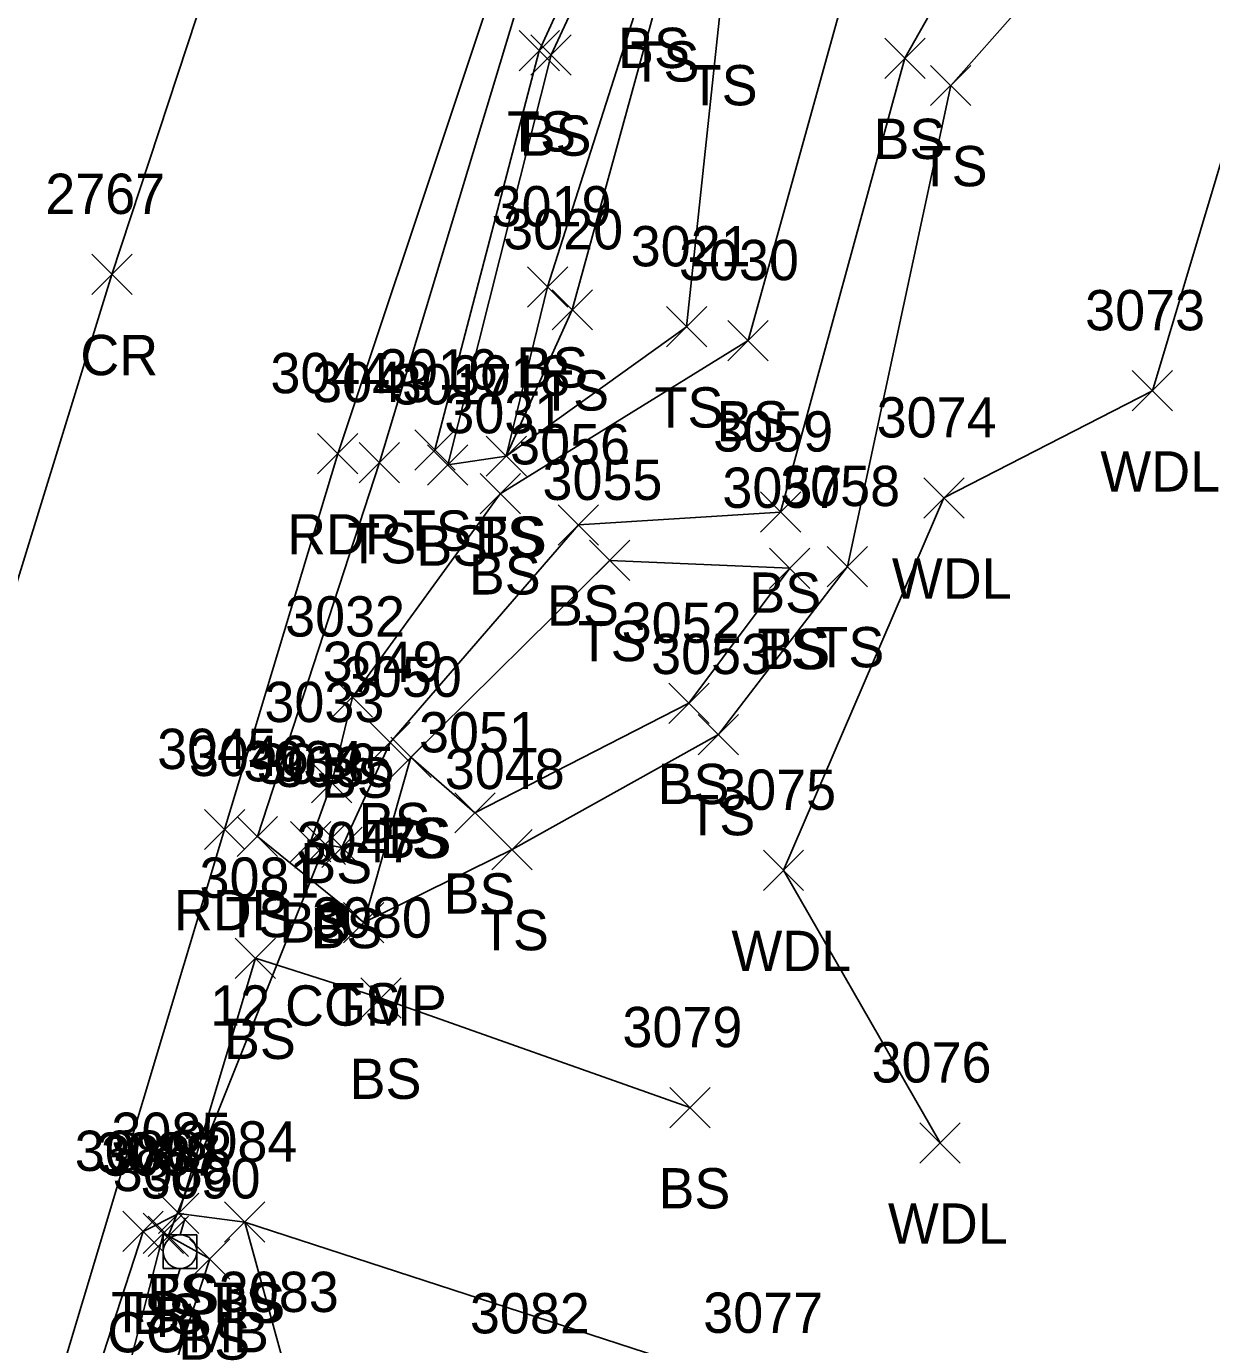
# Model space of a CAD drawing. Extents: x 1678863 to 1683592, y 407783 to 418211.
# Drawn here: x 1680507.9 to 1680566.7, y 415261.2 to 415326.6 of the extents above; entities that cross this region are included whole.
import ezdxf

# ---------------------------------------------------------------- set-up
doc = ezdxf.new("R2010")
doc.units = 0
for name, color, linetype in [('D_A', 7, 'Continuous'), ('D_C', 7, 'Continuous'), ('D_I', 7, 'Continuous'), ('D_TIC', 7, 'Continuous'), ('DCP', 7, 'Continuous'), ('L_A', 7, 'Continuous'), ('L_I', 7, 'Continuous'), ('L_TIC', 7, 'Continuous'), ('LAWA', 7, 'Continuous'), ('LELB', 7, 'Continuous'), ('P_A', 7, 'Continuous'), ('P_I', 7, 'Continuous'), ('P_TIC', 7, 'Continuous'), ('PET', 7, 'Continuous'), ('PRC', 7, 'Continuous'), ('U_A', 7, 'Continuous'), ('U_I', 7, 'Continuous'), ('UP', 7, 'Continuous')]:
    doc.layers.add(name, color=color, linetype=linetype)

msp = doc.modelspace()

# ---------------------------------------------------------------- linework, layer by layer
at = {"layer": 'D_TIC'}
for points in [[(1680521.768, 415285.028), (1680523.768, 415287.028)], [(1680523.768, 415285.028), (1680521.768, 415287.028)], [(1680513.981, 415265.583), (1680515.981, 415267.583)], [(1680515.981, 415265.583), (1680513.981, 415267.583)]]:
    msp.add_lwpolyline(points, dxfattribs=at)
at = {"layer": 'DCP'}
msp.add_lwpolyline([(1680522.768, 415286.028), (1680514.981, 415266.583)], dxfattribs=at)
at = {"layer": 'L_TIC'}
for points in [[(1680532.384, 415324.398), (1680534.384, 415326.398)], [(1680534.384, 415324.398), (1680532.384, 415326.398)], [(1680532.971, 415324.191), (1680534.971, 415326.191)], [(1680534.971, 415324.191), (1680532.971, 415326.191)], [(1680550.527, 415324.029), (1680552.527, 415326.029)], [(1680552.527, 415324.029), (1680550.527, 415326.029)], [(1680552.8, 415322.676), (1680554.8, 415324.676)], [(1680554.8, 415322.676), (1680552.8, 415324.676)], [(1680532.802, 415312.686), (1680534.802, 415314.686)], [(1680534.802, 415312.686), (1680532.802, 415314.686)], [(1680534.024, 415311.546), (1680536.024, 415313.546)], [(1680536.024, 415311.546), (1680534.024, 415313.546)], [(1680539.695, 415310.703), (1680541.695, 415312.703)], [(1680541.695, 415310.703), (1680539.695, 415312.703)], [(1680542.744, 415310.016), (1680544.744, 415312.016)], [(1680544.744, 415310.016), (1680542.744, 415312.016)], [(1680562.805, 415307.528), (1680564.805, 415309.528)], [(1680564.805, 415307.528), (1680562.805, 415309.528)], [(1680527.211, 415304.592), (1680529.211, 415306.592)], [(1680529.211, 415304.592), (1680527.211, 415306.592)], [(1680524.46, 415303.966), (1680526.46, 415305.966)], [(1680526.46, 415303.966), (1680524.46, 415305.966)], [(1680527.846, 415303.85), (1680529.846, 415305.85)], [(1680529.846, 415303.85), (1680527.846, 415305.85)], [(1680530.749, 415304.285), (1680532.749, 415306.285)], [(1680532.749, 415304.285), (1680530.749, 415306.285)], [(1680530.749, 415304.285), (1680532.749, 415306.285)], [(1680532.749, 415304.285), (1680530.749, 415306.285)], [(1680530.749, 415304.285), (1680532.749, 415306.285)], [(1680532.749, 415304.285), (1680530.749, 415306.285)], [(1680530.45, 415302.42), (1680532.45, 415304.42)], [(1680532.45, 415302.42), (1680530.45, 415304.42)], [(1680552.464, 415302.212), (1680554.464, 415304.212)], [(1680554.464, 415302.212), (1680552.464, 415304.212)], [(1680544.362, 415301.513), (1680546.362, 415303.513)], [(1680546.362, 415301.513), (1680544.362, 415303.513)], [(1680544.362, 415301.513), (1680546.362, 415303.513)], [(1680546.362, 415301.513), (1680544.362, 415303.513)], [(1680534.333, 415300.876), (1680536.333, 415302.876)], [(1680536.333, 415300.876), (1680534.333, 415302.876)], [(1680535.886, 415299.112), (1680537.886, 415301.112)], [(1680537.886, 415299.112), (1680535.886, 415301.112)], [(1680544.811, 415298.72), (1680546.811, 415300.72)], [(1680546.811, 415298.72), (1680544.811, 415300.72)], [(1680544.811, 415298.72), (1680546.811, 415300.72)], [(1680546.811, 415298.72), (1680544.811, 415300.72)], [(1680547.678, 415298.808), (1680549.678, 415300.808)], [(1680549.678, 415298.808), (1680547.678, 415300.808)], [(1680523.116, 415292.334), (1680525.116, 415294.334)], [(1680525.116, 415292.334), (1680523.116, 415294.334)], [(1680539.816, 415292.022), (1680541.816, 415294.022)], [(1680541.816, 415292.022), (1680539.816, 415294.022)], [(1680541.277, 415290.473), (1680543.277, 415292.473)], [(1680543.277, 415290.473), (1680541.277, 415292.473)], [(1680524.988, 415290.081), (1680526.988, 415292.081)], [(1680526.988, 415290.081), (1680524.988, 415292.081)], [(1680526.021, 415289.344), (1680528.021, 415291.344)], [(1680528.021, 415289.344), (1680526.021, 415291.344)], [(1680526.021, 415289.344), (1680528.021, 415291.344)], [(1680528.021, 415289.344), (1680526.021, 415291.344)], [(1680522.09, 415288.091), (1680524.09, 415290.091)], [(1680524.09, 415288.091), (1680522.09, 415290.091)], [(1680529.193, 415286.588), (1680531.193, 415288.588)], [(1680531.193, 415286.588), (1680529.193, 415288.588)], [(1680518.403, 415285.414), (1680520.403, 415287.414)], [(1680520.403, 415285.414), (1680518.403, 415287.414)], [(1680521.047, 415285.15), (1680523.047, 415287.15)], [(1680523.047, 415285.15), (1680521.047, 415287.15)], [(1680522.596, 415284.87), (1680524.596, 415286.87)], [(1680524.596, 415284.87), (1680522.596, 415286.87)], [(1680531.037, 415284.768), (1680533.037, 415286.768)], [(1680533.037, 415284.768), (1680531.037, 415286.768)], [(1680544.504, 415283.736), (1680546.504, 415285.736)], [(1680546.504, 415283.736), (1680544.504, 415285.736)], [(1680523.684, 415281.14), (1680525.684, 415283.14)], [(1680525.684, 415281.14), (1680523.684, 415283.14)], [(1680523.684, 415281.14), (1680525.684, 415283.14)], [(1680525.684, 415281.14), (1680523.684, 415283.14)], [(1680518.303, 415279.374), (1680520.303, 415281.374)], [(1680520.303, 415279.374), (1680518.303, 415281.374)], [(1680524.536, 415277.394), (1680526.536, 415279.394)], [(1680526.536, 415277.394), (1680524.536, 415279.394)], [(1680539.859, 415271.96), (1680541.859, 415273.96)], [(1680541.859, 415271.96), (1680539.859, 415273.96)], [(1680552.269, 415270.208), (1680554.269, 415272.208)], [(1680554.269, 415270.208), (1680552.269, 415272.208)], [(1680514.501, 415266.714), (1680516.501, 415268.714)], [(1680516.501, 415266.714), (1680514.501, 415268.714)], [(1680514.501, 415266.714), (1680516.501, 415268.714)], [(1680516.501, 415266.714), (1680514.501, 415268.714)], [(1680517.776, 415266.284), (1680519.776, 415268.284)], [(1680519.776, 415266.284), (1680517.776, 415268.284)], [(1680517.776, 415266.284), (1680519.776, 415268.284)], [(1680519.776, 415266.284), (1680517.776, 415268.284)], [(1680512.736, 415265.819), (1680514.736, 415267.819)], [(1680514.736, 415265.819), (1680512.736, 415267.819)], [(1680513.741, 415265.731), (1680515.741, 415267.731)], [(1680515.741, 415265.731), (1680513.741, 415267.731)], [(1680513.741, 415265.731), (1680515.741, 415267.731)], [(1680515.741, 415265.731), (1680513.741, 415267.731)], [(1680516.038, 415264.455), (1680518.038, 415266.455)], [(1680518.038, 415264.455), (1680516.038, 415266.455)]]:
    msp.add_lwpolyline(points, dxfattribs=at)
at = {"layer": 'LAWA'}
msp.add_lwpolyline([(1680578.203, 415359.452), (1680575.485, 415347.238), (1680570.126, 415329.641), (1680563.805, 415308.528), (1680553.464, 415303.212), (1680545.504, 415284.736), (1680553.269, 415271.208)], dxfattribs=at)
at = {"layer": 'LELB'}
for points in [[(1680602.77, 415511.813), (1680588.551, 415474.847), (1680576.233, 415446.787), (1680565.973, 415419.387), (1680554.329, 415388.441), (1680545.734, 415364.19), (1680536.087, 415340.183), (1680525.46, 415304.966), (1680519.403, 415286.414), (1680524.684, 415282.14), (1680532.037, 415285.768), (1680542.277, 415291.473), (1680548.678, 415299.808), (1680553.8, 415323.676), (1680564.168, 415335.395), (1680560.175, 415349.321), (1680559.787, 415354.793), (1680578.203, 415359.452)], [(1680557.841, 415377.831), (1680556.805, 415359.6), (1680544.299, 415350.764), (1680539.306, 415338.278), (1680533.384, 415325.398), (1680528.211, 415305.592)], [(1680575.848, 415361.42), (1680558.964, 415357.242), (1680544.703, 415348.394), (1680539.927, 415338.017), (1680533.971, 415325.191), (1680528.846, 415304.85), (1680531.749, 415305.285), (1680533.802, 415313.686), (1680538.856, 415329.543), (1680546.23, 415344.908), (1680555.699, 415348.007), (1680549.823, 415332.881), (1680543.744, 415311.016), (1680531.45, 415303.42), (1680524.116, 415293.334), (1680523.09, 415289.091), (1680522.047, 415286.15), (1680523.596, 415285.87), (1680525.988, 415291.081), (1680535.333, 415301.876), (1680545.362, 415302.513)], [(1680545.362, 415302.513), (1680551.527, 415325.029), (1680557.902, 415336.325), (1680559.665, 415349.006), (1680558.812, 415355.428), (1680578.193, 415360.635)], [(1680531.749, 415305.285), (1680535.024, 415312.546), (1680539.504, 415328.87), (1680547.641, 415344.142), (1680549.369, 415341.759)], [(1680531.749, 415305.285), (1680540.695, 415311.703), (1680542.393, 415327.691), (1680549.369, 415341.759)], [(1680524.684, 415282.14), (1680527.021, 415290.344), (1680536.886, 415300.112), (1680545.811, 415299.72)], [(1680527.021, 415290.344), (1680530.193, 415287.588), (1680540.816, 415293.022), (1680545.811, 415299.72)], [(1680540.859, 415272.96), (1680525.536, 415278.394), (1680519.303, 415280.374), (1680515.501, 415267.714)], [(1680520.83, 415259.82), (1680518.776, 415267.284), (1680515.501, 415267.714), (1680513.736, 415266.819), (1680508.012, 415249.22), (1680496.938, 415211.172), (1680488.875, 415180.262), (1680484.972, 415164.774), (1680487.905, 415164.19)], [(1680544.861, 415258.786), (1680518.776, 415267.284)], [(1680514.741, 415266.731), (1680509.982, 415248.247), (1680498.716, 415210.988), (1680490.74, 415179.498), (1680486.259, 415166.094), (1680488.034, 415165.412)], [(1680514.741, 415266.731), (1680517.038, 415265.455), (1680511.315, 415247.956), (1680499.763, 415210.565), (1680491.714, 415179.379), (1680488.034, 415165.412)]]:
    msp.add_lwpolyline(points, dxfattribs=at)
at = {"layer": 'P_TIC'}
for points in [[(1680511.187, 415313.302), (1680513.187, 415315.302)], [(1680513.187, 415313.302), (1680511.187, 415315.302)], [(1680522.389, 415304.407), (1680524.389, 415306.407)], [(1680524.389, 415304.407), (1680522.389, 415306.407)], [(1680516.773, 415285.761), (1680518.773, 415287.761)], [(1680518.773, 415285.761), (1680516.773, 415287.761)]]:
    msp.add_lwpolyline(points, dxfattribs=at)
at = {"layer": 'PET'}
msp.add_lwpolyline([(1680714.618, 415736.113), (1680695.558, 415699.429), (1680676.824, 415662.603), (1680663.451, 415636.865), (1680649.234, 415610.254), (1680634.131, 415580.725), (1680618.235, 415547.606), (1680602.164, 415512.053), (1680586.293, 415476.007), (1680574.611, 415447.702), (1680563.893, 415420.312), (1680552.332, 415389.01), (1680543.497, 415364.712), (1680535.144, 415340.605), (1680523.389, 415305.407), (1680517.773, 415286.761), (1680506.724, 415249.991), (1680495.796, 415211.549), (1680487.745, 415180.8)], dxfattribs=at)
at = {"layer": 'PRC'}
msp.add_lwpolyline([(1680684.221, 415706.228), (1680664.503, 415668.421), (1680651.646, 415643.034), (1680631.648, 415605.569), (1680616.996, 415575.826), (1680596.478, 415533.869), (1680584.461, 415507.136), (1680569.154, 415472.456), (1680556.962, 415440.736), (1680549.081, 415420.646), (1680536.221, 415384.732), (1680523.379, 415348.305), (1680512.187, 415314.302), (1680500.031, 415274.899), (1680490.658, 415243.579), (1680481.594, 415211.169), (1680473.057, 415178.672)], dxfattribs=at)
at = {"layer": 'UP'}
for p, q in [((1680515.816, 415267.486), (1680515.566, 415266.652)), ((1680514.733, 415264.986), (1680514.733, 415266.652)), ((1680514.733, 415266.652), (1680516.4, 415266.652)), ((1680516.4, 415266.652), (1680516.4, 415264.986)), ((1680515.566, 415265.819), (1680515.566, 415265.819)), ((1680516.4, 415264.986), (1680514.733, 415264.986)), ((1680515.316, 415264.152), (1680515.566, 415264.986))]:
    msp.add_line(p, q, dxfattribs=at)
msp.add_circle((1680515.566, 415265.819), 0.833, dxfattribs=at)

# ---------------------------------------------------------------- texts
at = {"layer": 'D_A'}
for p in [(1680522.146, 415281.028), (1680514.359, 415261.583)]:
    msp.add_text('P', height=2, dxfattribs=at).set_placement(p)
at = {"layer": 'D_C'}
msp.add_text('12 CGMP', height=2, dxfattribs=at).set_placement((1680517.059, 415277.028))
at = {"layer": 'D_I'}
for s, p in [('3036', (1680519.374, 415289.028)), ('3087', (1680511.643, 415269.583))]:
    msp.add_text(s, height=2, dxfattribs=at).set_placement(p)
at = {"layer": 'L_A'}
for s, p in [('BS', (1680537.297, 415324.543)), ('TS', (1680537.914, 415323.87)), ('TS', (1680540.802, 415322.691)), ('TS', (1680531.793, 415320.398)), ('BS', (1680532.412, 415320.191)), ('BS', (1680549.967, 415320.029)), ('TS', (1680552.21, 415318.676)), ('BS', (1680532.243, 415308.686)), ('TS', (1680533.433, 415307.546)), ('TS', (1680539.105, 415306.703)), ('BS', (1680542.185, 415306.016)), ('WDL', (1680561.223, 415303.528)), ('TS', (1680526.621, 415300.592)), ('TS', (1680523.87, 415299.966)), ('TS', (1680530.159, 415300.285)), ('TS', (1680530.159, 415300.285)), ('BS', (1680530.19, 415300.285)), ('BS', (1680527.286, 415299.85)), ('BS', (1680529.891, 415298.42)), ('WDL', (1680550.882, 415298.212)), ('BS', (1680543.803, 415297.513)), ('BS', (1680543.803, 415297.513)), ('BS', (1680533.774, 415296.876)), ('TS', (1680535.295, 415295.112)), ('TS', (1680544.22, 415294.72)), ('BS', (1680544.251, 415294.72)), ('TS', (1680547.088, 415294.808)), ('BS', (1680522.557, 415288.334)), ('BS', (1680539.257, 415288.022)), ('TS', (1680540.686, 415286.473)), ('BS', (1680524.429, 415286.081)), ('TS', (1680525.43, 415285.344)), ('BS', (1680525.462, 415285.344)), ('BS', (1680521.531, 415284.091)), ('BS', (1680528.634, 415282.588)), ('TS', (1680517.812, 415281.414)), ('BS', (1680520.488, 415281.15)), ('BS', (1680522.037, 415280.87)), ('TS', (1680530.447, 415280.768)), ('WDL', (1680542.922, 415279.736)), ('TS', (1680523.094, 415277.14)), ('TS', (1680523.094, 415277.14)), ('BS', (1680517.744, 415275.374)), ('BS', (1680523.977, 415273.394)), ('BS', (1680539.3, 415267.96)), ('WDL', (1680550.686, 415266.208)), ('TS', (1680513.91, 415262.714)), ('BS', (1680513.942, 415262.714)), ('TS', (1680517.185, 415262.284)), ('BS', (1680517.217, 415262.284)), ('TS', (1680512.146, 415261.819)), ('BS', (1680513.182, 415261.731)), ('BS', (1680513.182, 415261.731)), ('BS', (1680515.479, 415260.455))]:
    msp.add_text(s, height=2, dxfattribs=at).set_placement(p)
at = {"layer": 'L_I'}
for s, p in [('3019', (1680531.023, 415316.686)), ('3020', (1680531.598, 415315.546)), ('3021', (1680537.924, 415314.703)), ('3030', (1680540.319, 415314.016)), ('3073', (1680560.467, 415311.528)), ('3016', (1680525.384, 415308.592)), ('3043', (1680522.122, 415307.966)), ('3017', (1680526.074, 415307.85)), ('3018', (1680528.978, 415308.285)), ('3018', (1680528.978, 415308.285)), ('3018', (1680528.978, 415308.285)), ('3031', (1680528.679, 415306.42)), ('3074', (1680550.126, 415306.212)), ('3059', (1680542.016, 415305.513)), ('3059', (1680542.016, 415305.513)), ('3056', (1680531.94, 415304.876)), ('3055', (1680533.547, 415303.112)), ('3057', (1680542.472, 415302.72)), ('3057', (1680542.472, 415302.72)), ('3058', (1680545.34, 415302.808)), ('3032', (1680520.778, 415296.334)), ('3052', (1680537.477, 415296.022)), ('3049', (1680522.641, 415294.081)), ('3053', (1680538.938, 415294.473)), ('3050', (1680523.596, 415293.344)), ('3050', (1680523.596, 415293.344)), ('3033', (1680519.752, 415292.091)), ('3051', (1680527.421, 415290.588)), ('3046', (1680516.009, 415289.414)), ('3034', (1680518.709, 415289.15)), ('3035', (1680520.257, 415288.87)), ('3048', (1680528.699, 415288.768)), ('3075', (1680542.166, 415287.736)), ('3047', (1680521.345, 415285.14)), ('3047', (1680521.345, 415285.14)), ('3081', (1680516.532, 415283.374)), ('3080', (1680522.111, 415281.394)), ('3079', (1680537.513, 415275.96)), ('3076', (1680549.875, 415274.208)), ('3085', (1680512.162, 415270.714)), ('3085', (1680512.162, 415270.714)), ('3086', (1680510.343, 415269.819)), ('3084', (1680515.437, 415270.284)), ('3084', (1680515.437, 415270.284)), ('3089', (1680511.395, 415269.731)), ('3089', (1680511.395, 415269.731)), ('3090', (1680513.613, 415268.455)), ('3083', (1680517.491, 415262.82)), ('3083', (1680517.491, 415262.82)), ('3077', (1680541.522, 415261.786))]:
    msp.add_text(s, height=2, dxfattribs=at).set_placement(p)
at = {"layer": 'P_A'}
for s, p in [('CR', (1680510.62, 415309.302)), ('RDP', (1680520.877, 415300.407)), ('RDP', (1680515.261, 415281.761))]:
    msp.add_text(s, height=2, dxfattribs=at).set_placement(p)
at = {"layer": 'P_I'}
for s, p in [('2767', (1680508.88, 415317.302)), ('3044', (1680520.05, 415308.407)), ('3045', (1680514.434, 415289.761))]:
    msp.add_text(s, height=2, dxfattribs=at).set_placement(p)
at = {"layer": 'U_A'}
msp.add_text('COMB', height=2, dxfattribs=at).set_placement((1680511.952, 415260.819))
at = {"layer": 'U_I'}
for s, p in [('3088', (1680512.228, 415268.819)), ('3082', (1680529.948, 415261.76))]:
    msp.add_text(s, height=2, dxfattribs=at).set_placement(p)

doc.saveas('drawing.dxf')
